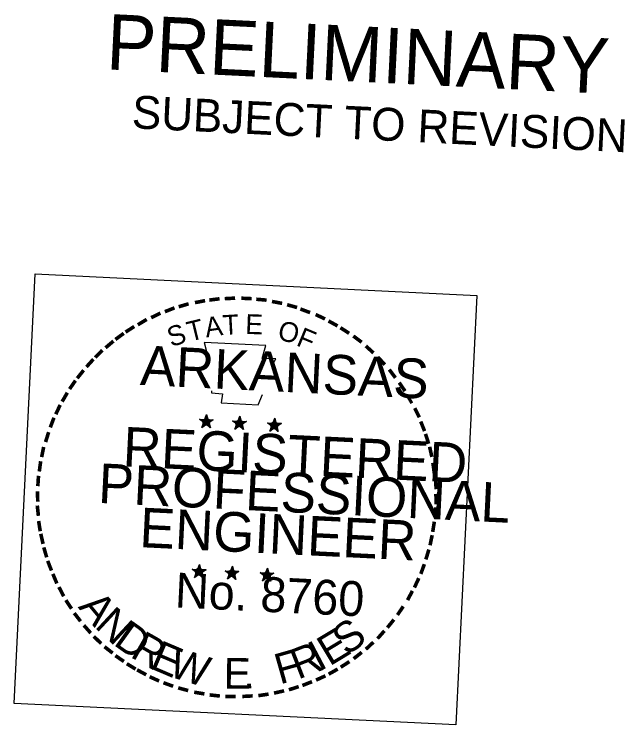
# Model space of a CAD drawing. Extents: x 668933 to 670801, y 741155 to 743955.
# Drawn here: x 669099.6 to 669176.7, y 743722.6 to 743812.3 of the extents above; entities that cross this region are included whole.
import ezdxf

# ---------------------------------------------------------------- set-up
doc = ezdxf.new("R2010")
doc.units = 0
doc.layers.add('R_Border PE', color=7, linetype='Continuous')
doc.layers.add('R_Border Prem', color=7, linetype='Continuous')

msp = doc.modelspace()

# ---------------------------------------------------------------- linework, layer by layer
at = {"layer": 'R_Border PE'}
for p, q in [((669122.995, 743761.184), (669123.856, 743760.867)), ((669122.995, 743761.184), (669123.642, 743761.102)), ((669122.995, 743761.184), (669123.639, 743761.052)), ((669122.995, 743761.184), (669123.612, 743761.004)), ((669122.995, 743761.184), (669123.607, 743760.904)), ((669122.995, 743761.184), (669123.58, 743760.855)), ((669122.995, 743761.184), (669123.577, 743760.805)), ((669123.901, 743761.791), (669123.745, 743761.172)), ((669123.901, 743761.791), (669123.769, 743761.146)), ((669123.901, 743761.791), (669123.845, 743761.168)), ((669123.856, 743760.867), (669123.901, 743761.791)), ((669124.743, 743761.099), (669123.856, 743760.867)), ((669123.901, 743761.791), (669124.044, 743761.133)), ((669123.901, 743761.791), (669123.995, 743761.16)), ((669123.901, 743761.791), (669123.945, 743761.163)), ((669124.743, 743761.099), (669123.966, 743761.087)), ((669124.743, 743761.099), (669124.01, 743760.959)), ((669124.743, 743761.099), (669124.013, 743761.009)), ((669124.743, 743761.099), (669124.183, 743760.901)), ((669124.743, 743761.099), (669124.231, 743760.873)), ((669124.743, 743761.099), (669124.255, 743760.847)), ((669128.071, 743761.588), (669127.915, 743760.97)), ((669128.071, 743761.588), (669127.939, 743760.944)), ((669128.071, 743761.588), (669127.99, 743760.966)), ((669128.026, 743760.664), (669128.071, 743761.588)), ((669128.071, 743761.588), (669128.214, 743760.93)), ((669128.071, 743761.588), (669128.165, 743760.958)), ((669128.071, 743761.588), (669128.09, 743760.961)), ((669132.488, 743761.324), (669132.309, 743760.731)), ((669132.488, 743761.324), (669132.358, 743760.704)), ((669132.488, 743761.324), (669132.408, 743760.702)), ((669132.444, 743760.425), (669132.488, 743761.324)), ((669132.488, 743761.324), (669132.633, 743760.691)), ((669132.488, 743761.324), (669132.583, 743760.693)), ((669132.488, 743761.324), (669132.509, 743760.722)), ((669123.295, 743760.143), (669123.856, 743760.867)), ((669123.295, 743760.143), (669123.604, 743760.829)), ((669123.295, 743760.143), (669123.625, 743760.753)), ((669123.295, 743760.143), (669123.674, 743760.725)), ((669123.295, 743760.143), (669123.846, 743760.667)), ((669123.295, 743760.143), (669123.745, 743760.647)), ((669123.295, 743760.143), (669123.867, 743760.591)), ((669124.369, 743760.091), (669123.842, 743760.592)), ((669124.369, 743760.091), (669123.846, 743760.667)), ((669124.369, 743760.091), (669123.856, 743760.867)), ((669124.369, 743760.091), (669123.945, 743760.637)), ((669124.369, 743760.091), (669124.024, 743760.733)), ((669124.369, 743760.091), (669124.054, 743760.832)), ((669124.369, 743760.091), (669124.105, 743760.855)), ((669127.165, 743760.981), (669128.026, 743760.664)), ((669127.165, 743760.981), (669127.812, 743760.9)), ((669127.165, 743760.981), (669127.81, 743760.85)), ((669127.165, 743760.981), (669127.782, 743760.801)), ((669127.165, 743760.981), (669127.752, 743760.702)), ((669127.165, 743760.981), (669127.75, 743760.653)), ((669127.165, 743760.981), (669127.747, 743760.603)), ((669127.465, 743759.941), (669128.026, 743760.664)), ((669127.465, 743759.941), (669127.774, 743760.626)), ((669127.465, 743759.941), (669127.795, 743760.55)), ((669127.465, 743759.941), (669127.844, 743760.523)), ((669127.465, 743759.941), (669128.016, 743760.464)), ((669127.465, 743759.941), (669127.915, 743760.444)), ((669127.465, 743759.941), (669128.037, 743760.388)), ((669128.539, 743759.888), (669128.012, 743760.389)), ((669128.539, 743759.888), (669128.016, 743760.464)), ((669128.913, 743760.896), (669128.026, 743760.664)), ((669128.539, 743759.888), (669128.026, 743760.664)), ((669128.539, 743759.888), (669128.115, 743760.435)), ((669128.913, 743760.896), (669128.137, 743760.884)), ((669128.913, 743760.896), (669128.18, 743760.757)), ((669128.913, 743760.896), (669128.183, 743760.807)), ((669128.539, 743759.888), (669128.195, 743760.531)), ((669128.539, 743759.888), (669128.224, 743760.629)), ((669128.539, 743759.888), (669128.275, 743760.652)), ((669128.913, 743760.896), (669128.353, 743760.698)), ((669128.913, 743760.896), (669128.402, 743760.671)), ((669128.913, 743760.896), (669128.425, 743760.645)), ((669131.584, 743760.742), (669132.444, 743760.425)), ((669131.584, 743760.742), (669132.229, 743760.635)), ((669131.584, 743760.742), (669132.202, 743760.587)), ((669131.584, 743760.742), (669132.201, 743760.562)), ((669131.584, 743760.742), (669132.171, 743760.463)), ((669131.584, 743760.742), (669132.168, 743760.413)), ((669131.584, 743760.742), (669132.166, 743760.363)), ((669131.859, 743759.702), (669132.444, 743760.425)), ((669131.859, 743759.702), (669132.192, 743760.387)), ((669131.859, 743759.702), (669132.214, 743760.311)), ((669131.859, 743759.702), (669132.262, 743760.283)), ((669131.859, 743759.702), (669132.435, 743760.225)), ((669131.859, 743759.702), (669132.334, 743760.205)), ((669132.932, 743759.65), (669132.435, 743760.225)), ((669133.332, 743760.657), (669132.444, 743760.425)), ((669132.932, 743759.65), (669132.444, 743760.425)), ((669132.932, 743759.65), (669132.533, 743760.195)), ((669133.332, 743760.657), (669132.555, 743760.644)), ((669133.332, 743760.657), (669132.599, 743760.517)), ((669133.332, 743760.657), (669132.601, 743760.567)), ((669132.932, 743759.65), (669132.613, 743760.291)), ((669132.932, 743759.65), (669132.643, 743760.39)), ((669132.932, 743759.65), (669132.693, 743760.387)), ((669133.332, 743760.657), (669132.771, 743760.459)), ((669133.332, 743760.657), (669132.795, 743760.433)), ((669133.332, 743760.657), (669132.844, 743760.405)), ((669131.859, 743759.702), (669132.456, 743760.149)), ((669132.932, 743759.65), (669132.431, 743760.15)), ((669122.077, 743742.281), (669122.938, 743741.964)), ((669122.077, 743742.281), (669122.723, 743742.175)), ((669122.077, 743742.281), (669122.695, 743742.126)), ((669122.077, 743742.281), (669122.694, 743742.101)), ((669122.077, 743742.281), (669122.664, 743742.002)), ((669122.077, 743742.281), (669122.662, 743741.952)), ((669122.077, 743742.281), (669122.659, 743741.902)), ((669122.981, 743742.863), (669122.803, 743742.271)), ((669122.981, 743742.863), (669122.851, 743742.243)), ((669122.981, 743742.863), (669122.901, 743742.241)), ((669122.938, 743741.964), (669122.981, 743742.863)), ((669122.981, 743742.863), (669123.126, 743742.23)), ((669122.981, 743742.863), (669123.076, 743742.233)), ((669122.981, 743742.863), (669123.001, 743742.236)), ((669127.152, 743742.66), (669126.973, 743742.068)), ((669127.152, 743742.66), (669127.021, 743742.041)), ((669127.152, 743742.66), (669127.071, 743742.039)), ((669127.108, 743741.761), (669127.152, 743742.66)), ((669127.152, 743742.66), (669127.271, 743742.029)), ((669127.152, 743742.66), (669127.246, 743742.03)), ((669127.152, 743742.66), (669127.171, 743742.034)), ((669131.57, 743742.421), (669131.39, 743741.804)), ((669131.57, 743742.421), (669131.44, 743741.801)), ((669131.57, 743742.421), (669131.49, 743741.799)), ((669131.526, 743741.522), (669131.57, 743742.421)), ((669131.57, 743742.421), (669131.69, 743741.789)), ((669131.57, 743742.421), (669131.665, 743741.79)), ((669131.57, 743742.421), (669131.59, 743741.794)), ((669122.352, 743741.241), (669122.938, 743741.964)), ((669122.352, 743741.241), (669122.686, 743741.926)), ((669122.352, 743741.241), (669122.706, 743741.825)), ((669122.352, 743741.241), (669122.755, 743741.798)), ((669122.352, 743741.241), (669122.928, 743741.764)), ((669122.352, 743741.241), (669122.827, 743741.744)), ((669122.352, 743741.241), (669122.924, 743741.689)), ((669123.426, 743741.189), (669122.899, 743741.69)), ((669123.426, 743741.189), (669122.927, 743741.739)), ((669123.825, 743742.196), (669122.938, 743741.964)), ((669123.426, 743741.189), (669122.938, 743741.964)), ((669123.426, 743741.189), (669123.002, 743741.736)), ((669123.825, 743742.196), (669123.049, 743742.184)), ((669123.825, 743742.196), (669123.092, 743742.057)), ((669123.825, 743742.196), (669123.095, 743742.106)), ((669123.426, 743741.189), (669123.107, 743741.831)), ((669123.426, 743741.189), (669123.111, 743741.93)), ((669123.426, 743741.189), (669123.186, 743741.927)), ((669123.825, 743742.196), (669123.24, 743741.999)), ((669123.825, 743742.196), (669123.289, 743741.972)), ((669123.825, 743742.196), (669123.336, 743741.92)), ((669126.247, 743742.079), (669127.108, 743741.761)), ((669126.247, 743742.079), (669126.868, 743741.973)), ((669126.247, 743742.079), (669126.865, 743741.923)), ((669126.247, 743742.079), (669126.864, 743741.898)), ((669126.247, 743742.079), (669126.834, 743741.8)), ((669126.247, 743742.079), (669126.832, 743741.75)), ((669126.247, 743742.079), (669126.83, 743741.7)), ((669126.522, 743741.039), (669127.108, 743741.761)), ((669126.522, 743741.039), (669126.856, 743741.724)), ((669126.522, 743741.039), (669126.876, 743741.623)), ((669126.522, 743741.039), (669126.925, 743741.595)), ((669126.522, 743741.039), (669127.098, 743741.562)), ((669126.522, 743741.039), (669126.997, 743741.542)), ((669126.522, 743741.039), (669127.095, 743741.487)), ((669127.596, 743740.987), (669127.07, 743741.488)), ((669127.596, 743740.987), (669127.097, 743741.537)), ((669127.97, 743741.995), (669127.108, 743741.761)), ((669127.596, 743740.987), (669127.108, 743741.761)), ((669127.596, 743740.987), (669127.172, 743741.533)), ((669127.97, 743741.995), (669127.219, 743741.981)), ((669127.97, 743741.995), (669127.263, 743741.854)), ((669127.97, 743741.995), (669127.265, 743741.904)), ((669127.596, 743740.987), (669127.277, 743741.628)), ((669127.596, 743740.987), (669127.281, 743741.728)), ((669127.596, 743740.987), (669127.356, 743741.724)), ((669127.97, 743741.995), (669127.41, 743741.797)), ((669127.97, 743741.995), (669127.459, 743741.769)), ((669127.97, 743741.995), (669127.506, 743741.717)), ((669130.666, 743741.839), (669131.526, 743741.522)), ((669130.666, 743741.839), (669131.286, 743741.734)), ((669130.666, 743741.839), (669131.284, 743741.684)), ((669130.666, 743741.839), (669131.257, 743741.635)), ((669130.666, 743741.839), (669131.253, 743741.56)), ((669130.666, 743741.839), (669131.224, 743741.486)), ((669130.666, 743741.839), (669131.222, 743741.437)), ((669130.941, 743740.799), (669131.526, 743741.522)), ((669130.941, 743740.799), (669131.249, 743741.485)), ((669130.941, 743740.799), (669131.269, 743741.384)), ((669130.941, 743740.799), (669131.343, 743741.356)), ((669132.389, 743741.755), (669131.526, 743741.522)), ((669132.014, 743740.747), (669131.526, 743741.522)), ((669132.389, 743741.755), (669131.637, 743741.742)), ((669132.014, 743740.747), (669131.669, 743741.365)), ((669132.389, 743741.755), (669131.681, 743741.614)), ((669132.389, 743741.755), (669131.684, 743741.664)), ((669132.014, 743740.747), (669131.7, 743741.488)), ((669132.014, 743740.747), (669131.75, 743741.486)), ((669132.389, 743741.755), (669131.829, 743741.557)), ((669132.389, 743741.755), (669131.876, 743741.505)), ((669132.389, 743741.755), (669131.9, 743741.479)), ((669130.941, 743740.799), (669131.416, 743741.302)), ((669130.941, 743740.799), (669131.491, 743741.298)), ((669130.941, 743740.799), (669131.513, 743741.247)), ((669132.014, 743740.747), (669131.487, 743741.223)), ((669132.014, 743740.747), (669131.491, 743741.298)), ((669132.014, 743740.747), (669131.59, 743741.293))]:
    msp.add_line(p, q, dxfattribs=at)
for points in [[(669123.59, 743770.866), (669124.139, 743768.762)], [(669132.244, 743768.143), (669132.627, 743768.826), (669130.902, 743768.859), (669131.356, 743770.489), (669123.59, 743770.866)], [(669124.521, 743764.764), (669124.51, 743764.539), (669125.906, 743764.421), (669125.724, 743763.254), (669130.393, 743763.027), (669130.957, 743764.326)], [(669123.901, 743761.791), (669124.369, 743760.091), (669122.995, 743761.184), (669124.743, 743761.099), (669123.295, 743760.143), (669123.901, 743761.791)], [(669128.071, 743761.588), (669128.539, 743759.888), (669127.165, 743760.981), (669128.913, 743760.896), (669127.465, 743759.941), (669128.071, 743761.588)], [(669132.488, 743761.324), (669132.932, 743759.65), (669131.584, 743760.742), (669133.332, 743760.657), (669131.859, 743759.702), (669132.488, 743761.324)], [(669122.981, 743742.863), (669123.426, 743741.189), (669122.077, 743742.281), (669123.825, 743742.196), (669122.352, 743741.241), (669122.981, 743742.863)], [(669127.152, 743742.66), (669127.596, 743740.987), (669126.247, 743742.079), (669127.97, 743741.995), (669126.522, 743741.039), (669127.152, 743742.66)], [(669131.57, 743742.421), (669132.014, 743740.747), (669130.666, 743741.839), (669132.389, 743741.755), (669130.941, 743740.799), (669131.57, 743742.421)]]:
    msp.add_lwpolyline(points, dxfattribs=at)
for centre, radius in [((669123.863, 743760.864), 0.431), ((669123.863, 743760.864), 0.39), ((669123.863, 743760.864), 0.361), ((669123.863, 743760.864), 0.332), ((669123.863, 743760.864), 0.289), ((669123.863, 743760.864), 0.269), ((669123.863, 743760.864), 0.248), ((669123.863, 743760.864), 0.213), ((669128.031, 743760.662), 0.431), ((669123.863, 743760.864), 0.187), ((669123.863, 743760.864), 0.155), ((669123.863, 743760.864), 0.124), ((669123.863, 743760.864), 0.0924), ((669123.863, 743760.864), 0.0741), ((669123.863, 743760.864), 0.036), ((669128.031, 743760.662), 0.39), ((669128.031, 743760.662), 0.361), ((669128.031, 743760.662), 0.332), ((669128.031, 743760.662), 0.289), ((669128.031, 743760.662), 0.269), ((669128.031, 743760.662), 0.248), ((669128.031, 743760.662), 0.213), ((669128.031, 743760.662), 0.187), ((669128.031, 743760.662), 0.155), ((669128.031, 743760.662), 0.124), ((669128.031, 743760.662), 0.0924), ((669128.031, 743760.662), 0.0741), ((669128.031, 743760.662), 0.036), ((669132.442, 743760.418), 0.431), ((669132.442, 743760.418), 0.39), ((669132.442, 743760.418), 0.361), ((669132.442, 743760.418), 0.332), ((669132.442, 743760.418), 0.289), ((669132.442, 743760.418), 0.269), ((669132.442, 743760.418), 0.248), ((669132.442, 743760.418), 0.213), ((669132.442, 743760.418), 0.187), ((669132.442, 743760.418), 0.155), ((669132.442, 743760.418), 0.124), ((669132.442, 743760.418), 0.0924), ((669132.442, 743760.418), 0.0741), ((669132.442, 743760.418), 0.036), ((669122.934, 743741.954), 0.431), ((669122.934, 743741.954), 0.39), ((669122.934, 743741.954), 0.361), ((669122.934, 743741.954), 0.332), ((669122.934, 743741.954), 0.289), ((669122.934, 743741.954), 0.269), ((669122.934, 743741.954), 0.248), ((669122.934, 743741.954), 0.213), ((669122.934, 743741.954), 0.187), ((669122.934, 743741.954), 0.155), ((669122.934, 743741.954), 0.124), ((669122.934, 743741.954), 0.0924), ((669122.934, 743741.954), 0.0741), ((669122.934, 743741.954), 0.036), ((669127.102, 743741.752), 0.431), ((669127.102, 743741.752), 0.39), ((669127.102, 743741.752), 0.361), ((669127.102, 743741.752), 0.332), ((669127.102, 743741.752), 0.289), ((669127.102, 743741.752), 0.269), ((669127.102, 743741.752), 0.248), ((669127.102, 743741.752), 0.213), ((669127.102, 743741.752), 0.187), ((669127.102, 743741.752), 0.155), ((669127.102, 743741.752), 0.124), ((669127.102, 743741.752), 0.0924), ((669127.102, 743741.752), 0.0741), ((669127.102, 743741.752), 0.036), ((669131.514, 743741.509), 0.431), ((669131.514, 743741.509), 0.39), ((669131.514, 743741.509), 0.361), ((669131.514, 743741.509), 0.332), ((669131.514, 743741.509), 0.289), ((669131.514, 743741.509), 0.269), ((669131.514, 743741.509), 0.248), ((669131.514, 743741.509), 0.213), ((669131.514, 743741.509), 0.187), ((669131.514, 743741.509), 0.155), ((669131.514, 743741.509), 0.124), ((669131.514, 743741.509), 0.0924), ((669131.514, 743741.509), 0.0741), ((669131.514, 743741.509), 0.036)]:
    msp.add_circle(centre, radius, dxfattribs=at)
at = {"layer": 'R_Border Prem'}
msp.add_lwpolyline([(669102.248, 743779.53), (669157.982, 743776.823), (669155.35, 743722.639), (669099.616, 743725.345)], close=True, dxfattribs=at)

# ---------------------------------------------------------------- texts
at = {"layer": 'R_Border PE'}
for s, height, rotation, p in [('-', 3.999, 10.85007, (669122.483, 743774.349)), ('-', 4, 7.43927, (669124.2, 743774.666)), ('-', 3.999, 3.11674, (669126.037, 743774.852)), ('-', 3.999, 357.40615, (669127.968, 743774.934)), ('-', 4, 354.96296, (669129.789, 743774.82)), ('-', 4, 21.52713, (669118.975, 743773.243)), ('-', 3.999, 16.39601, (669120.581, 743773.841)), ('-', 4, 349.38165, (669131.63, 743774.581)), ('-', 4, 344.42481, (669133.415, 743774.219)), ('-', 4, 26.01174, (669117.363, 743772.52)), ('-', 4, 339.55612, (669134.968, 743773.743)), ('-', 4, 335.07501, (669136.789, 743773.104)), ('-', 4, 31.28349, (669115.82, 743771.669)), ('T', 2.499, 13.62352, (669121.744, 743770.981)), ('A', 2.5, 8.4331, (669123.847, 743771.505)), ('T', 2.5, 3.24268, (669125.99, 743771.826)), ('E', 2.5, 358.05226, (669128.75, 743771.967)), ('-', 4, 331.34101, (669138.33, 743772.353)), ('-', 3.999, 33.45166, (669114.325, 743770.766)), ('S', 2.499, 18.81394, (669119.431, 743770.267)), ('O', 2.499, 347.67142, (669132.745, 743771.248)), ('F', 2.499, 337.29058, (669135.089, 743770.558)), ('-', 3.999, 326.86082, (669139.744, 743771.584)), ('-', 3.999, 36.17058, (669113.105, 743769.874)), ('-', 3.999, 323.08258, (669141.299, 743770.607)), ('-', 3.999, 40.18217, (669111.955, 743768.878)), ('-', 4, 45.64297, (669110.773, 743767.734)), ('ARKANSAS', 5, 357.21992, (669115.447, 743765.53)), ('-', 4, 317.74963, (669142.77, 743769.459)), ('-', 4, 312.79851, (669144.209, 743768.163)), ('-', 3.999, 47.8341, (669109.716, 743766.584)), ('-', 4, 51.45239, (669108.623, 743765.211)), ('-', 3.999, 307.09965, (669145.565, 743766.721)), ('-', 4, 55.29055, (669107.735, 743763.927)), ('-', 3.999, 303.8721, (669146.791, 743765.159)), ('-', 3.999, 60.09127, (669106.887, 743762.442)), ('-', 3.5, 300.89521, (669147.945, 743763.677)), ('-', 3.999, 64.99419, (669106.164, 743760.95)), ('-', 4, 296.88827, (669148.67, 743762.115)), ('-', 3.999, 69.61439, (669105.538, 743759.403)), ('REGISTERED', 5, 357.21992, (669113.246, 743755.25)), ('-', 3.999, 291.88272, (669149.396, 743760.553)), ('-', 4, 72.68088, (669104.976, 743757.629)), ('-', 3.999, 287.79275, (669149.976, 743759.098)), ('-', 3.999, 78.42119, (669104.541, 743755.873)), ('-', 4, 282.34318, (669150.48, 743757.622)), ('-', 3.999, 82.40626, (669104.282, 743754.158)), ('-', 4, 277.76926, (669150.888, 743755.724)), ('PROFESSIONAL', 4.99995, 357.21992, (669110.144, 743750.645)), ('-', 4, 86.28216, (669104.122, 743752.414)), ('-', 4, 273.81608, (669151.22, 743753.806)), ('-', 3.999, 91.4158, (669104.134, 743750.586)), ('-', 4, 271.55003, (669151.282, 743751.976)), ('-', 3.999, 96.16785, (669104.229, 743748.93)), ('ENGINEER', 5, 357.21992, (669115.354, 743745.06)), ('-', 3.999, 267.16059, (669151.28, 743750.399)), ('-', 4, 98.93487, (669104.464, 743747.066)), ('-', 3.999, 260.73712, (669151.15, 743748.754)), ('-', 4, 102.67777, (669104.816, 743745.572)), ('-', 4, 258.21521, (669150.895, 743747.114)), ('-', 3.999, 106.30734, (669105.264, 743743.973)), ('-', 3.999, 252.98253, (669150.538, 743745.429)), ('-', 3.999, 111.28424, (669105.841, 743742.444)), ('-', 4, 250.08801, (669150.002, 743743.653)), ('-', 3.999, 112.94877, (669106.515, 743740.859)), ('No. 8760', 4.4, 357.21992, (669119.835, 743737.459)), ('-', 4, 245.10859, (669149.371, 743742.007)), ('-', 4, 117.66704, (669107.343, 743739.367)), ('-', 4, 241.83964, (669148.62, 743740.467)), ('A', 3.849, 309.69259, (669107.602, 743737.475)), ('-', 4, 123.11337, (669108.274, 743737.92)), ('-', 3.999, 127.93804, (669109.355, 743736.466)), ('N', 3.849, 317.05608, (669109.657, 743735)), ('-', 4, 236.29117, (669147.556, 743738.641)), ('-', 4, 231.06516, (669146.478, 743737.066)), ('-', 4, 131.44373, (669110.588, 743735.055)), ('D', 3.849, 324.41957, (669112.013, 743732.808)), ('S', 3.849, 36.94295, (669141.607, 743731.259)), ('R', 3.849, 330.39371, (669114.118, 743731.263)), ('E', 3.849, 31.10774, (669139.406, 743729.971)), ('-', 4, 228.47369, (669145.335, 743735.695)), ('-', 4, 136.15374, (669111.831, 743733.843)), ('-', 3.999, 141.86626, (669113.179, 743732.751)), ('E', 3.849, 336.9236, (669116.588, 743729.836)), ('W', 3.849, 342.75881, (669118.921, 743728.805)), ('R', 3.849, 21.24345, (669135.426, 743728.322)), ('I', 3.849, 27.77333, (669138.093, 743729.337)), ('-', 3.999, 222.98525, (669144.069, 743734.355)), ('-', 4, 145.30971, (669114.533, 743731.76)), ('F', 3.849, 15.82503, (669133.137, 743727.715)), ('-', 3.999, 218.30501, (669142.708, 743733.145)), ('E', 3.849, 359.50032, (669126.041, 743727.221)), ('-', 3.999, 212.95626, (669141.278, 743732.038)), ('-', 3.999, 148.79031, (669115.941, 743730.865)), ('-', 3.999, 151.82012, (669117.211, 743730.203)), ('-', 4, 209.46901, (669139.882, 743731.129)), ('-', 4, 155.78114, (669118.752, 743729.477)), ('-', 4, 204.57676, (669138.466, 743730.322)), ('-', 4, 160.01819, (669120.425, 743728.87)), ('-', 3.999, 201.47154, (669136.854, 743729.599)), ('-', 4, 164.77544, (669122.203, 743728.384)), ('.', 3.849, 5.33554, (669128.591, 743727.165)), ('-', 3.999, 192.69421, (669133.571, 743728.482)), ('-', 4, 197.93834, (669135.274, 743729)), ('-', 4, 170.33538, (669124.113, 743728.016)), ('-', 4, 173.73819, (669125.978, 743727.775)), ('-', 4, 178.81168, (669127.828, 743727.735)), ('-', 3.999, 183.03659, (669129.861, 743727.837)), ('-', 4, 188.50568, (669131.724, 743728.071))]:
    msp.add_text(s, height=height, rotation=rotation, dxfattribs=at).set_placement(p)
at = {"layer": 'R_Border Prem'}
for s, height, p in [('PRELIMINARY', 7.00001, (669111.136, 743805.348)), ('SUBJECT TO REVISION', 4.15022, (669114.395, 743797.922))]:
    msp.add_text(s, height=height, rotation=357.20084, dxfattribs=at).set_placement(p)

doc.saveas('drawing.dxf')
